// Mitsubishi GX Works2 project: 凌一PID案例   PLC: FX3U/FX3UC

PROGRAM MAIN
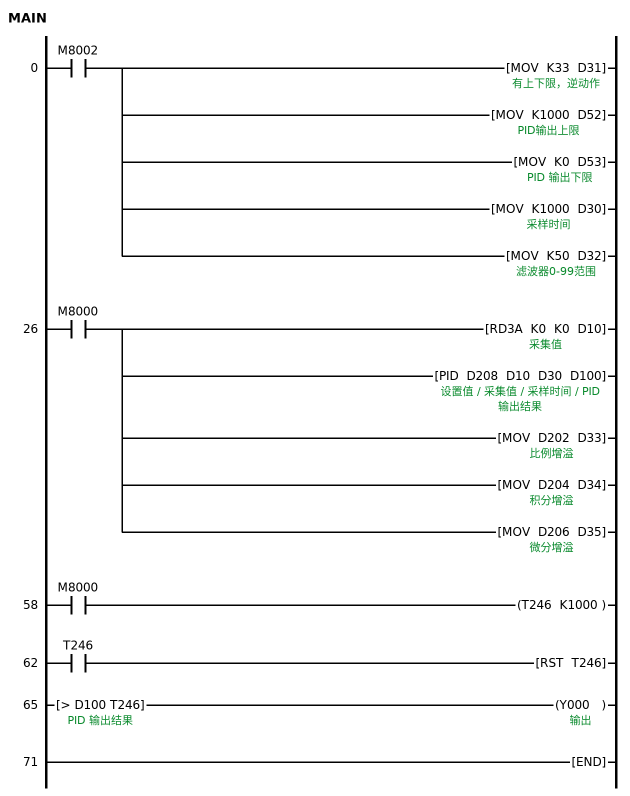
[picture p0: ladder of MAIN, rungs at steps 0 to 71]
0     LD      M8002
      MOV     K33 D31  ; 有上下限，逆动作
      MOV     K1000 D52  ; PID输出上限
      MOV     K0 D53  ; PID 输出下限
      MOV     K1000 D30  ; 采样时间
      MOV     K50 D32  ; 滤波器0-99范围
26    LD      M8000
      RD3A    K0 K0 D10  ; 采集值
      PID     D208 D10 D30 D100  ; 设置值 / PID 输出结果
      MOV     D202 D33  ; 比例增溢
      MOV     D204 D34  ; 积分增溢
      MOV     D206 D35  ; 微分增溢
58    LD      M8000
      OUT     T246 K1000
62    LD      T246
      RST     T246
65    LD>     D100 T246  ; PID 输出结果
      OUT     Y000  ; 输出
71    END
END_PROGRAM

// device comments not shown above
D0  ; 设定值
